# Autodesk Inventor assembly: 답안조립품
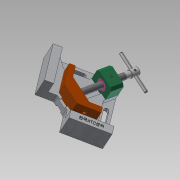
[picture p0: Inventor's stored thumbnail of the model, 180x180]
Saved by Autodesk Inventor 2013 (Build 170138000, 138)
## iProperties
Created: 2019-04
Part Number: 답안조립품
Document SubType Name: Assembly
Designer: Administrator
Author: Administrator
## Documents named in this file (11)
- C:\Users\Administrator\Desktop\490407V1017\답안조립품.iam
- C:\Users\Administrator\Desktop\490407V1017\리드스크류.ipt
- C:\Users\Administrator\Desktop\490407V1017\멈춤나사 M4x5.ipt
- C:\Users\Administrator\Desktop\490407V1017\멈춤나사 M4x10.ipt
- C:\Users\Administrator\Desktop\490407V1017\볼트 M4x16.ipt
- C:\Users\Administrator\Desktop\490407V1017\부시.ipt
- C:\Users\Administrator\Desktop\490407V1017\서포트.ipt
- C:\Users\Administrator\Desktop\490407V1017\조.ipt
- C:\Users\Administrator\Desktop\490407V1017\평행 핀 2.5x24.ipt
- C:\Users\Administrator\Desktop\490407V1017\핸들.ipt
- C:\Users\Administrator\Desktop\490407V1017\본체.ipt
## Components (1 placed, 1 different names)
1. 핸들:1
